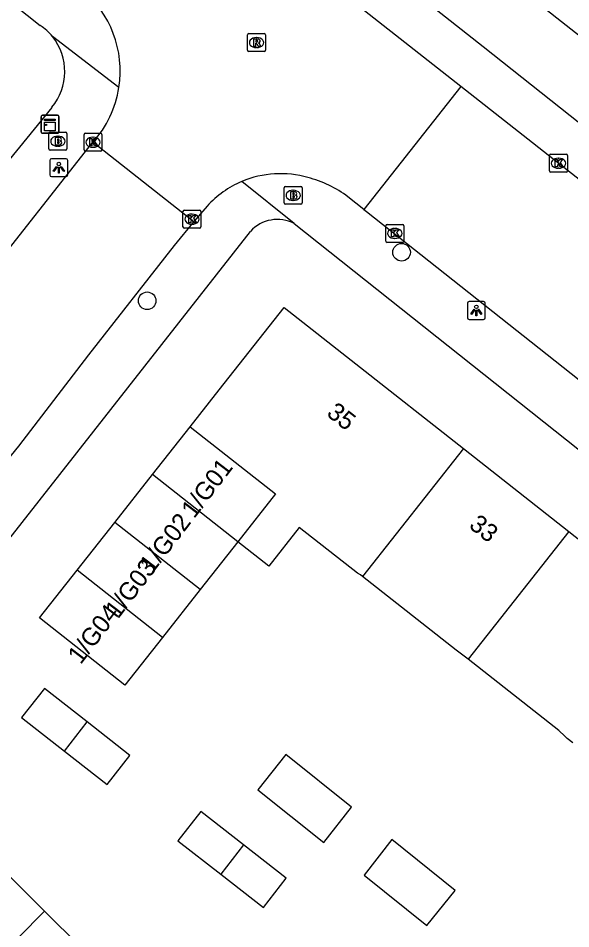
# Model space of a CAD drawing. Extents: x 159222 to 160346, y 381249 to 382166.
# Drawn here: x 160133.8 to 160164.6, y 381881.1 to 381931.9 of the extents above; entities that cross this region are included whole.
import ezdxf

# ---------------------------------------------------------------- set-up
doc = ezdxf.new("R2010")
doc.units = 0
for name, color, linetype in [('IMGEO_Boom', 7, 'Continuous'), ('IMGEO_Brandkraan', 7, 'Continuous'), ('IMGEO_Kast', 7, 'Continuous'), ('IMGEO_Kolk', 7, 'Continuous'), ('IMGEO_Lichtpunt', 7, 'Continuous'), ('IMGEO_Pand', 7, 'Continuous'), ('IMGEO_Pand_nummerreeks', 7, 'Continuous'), ('IMGEO_Rijbaan_lokaal_gesloten', 7, 'Continuous'), ('IMGEO_Rijbaan_lokaal_open', 7, 'Continuous'), ('IMGEO_Rioolput', 7, 'Continuous'), ('IMGEO_Voetpad_open', 7, 'Continuous')]:
    doc.layers.add(name, color=color, linetype=linetype)

msp = doc.modelspace()

# ---------------------------------------------------------------- linework, layer by layer
at = {"layer": 'IMGEO_Boom'}
for centre in [(160155.178, 381918.837), (160140.999, 381916.134)]:
    msp.add_circle(centre, 0.489, dxfattribs=at)
at = {"layer": 'IMGEO_Brandkraan'}
for p, q in [((160135.526, 381924.6), (160135.526, 381925.452)), ((160135.601, 381925.526), (160136.453, 381925.526)), ((160136.014, 381925.306), (160136.039, 381925.306)), ((160136.527, 381925.452), (160136.527, 381924.6)), ((160136.037, 381924.746), (160136.012, 381924.746)), ((160136.453, 381924.526), (160135.601, 381924.526)), ((160148.638, 381921.583), (160148.638, 381922.435)), ((160148.713, 381922.509), (160149.565, 381922.509)), ((160149.126, 381922.289), (160149.151, 381922.289)), ((160149.639, 381922.435), (160149.639, 381921.583)), ((160149.149, 381921.729), (160149.124, 381921.729)), ((160149.565, 381921.509), (160148.713, 381921.509))]:
    msp.add_line(p, q, dxfattribs=at)
for points in [[(160135.526, 381924.6), (160135.526, 381925.452)], [(160135.601, 381925.526), (160136.453, 381925.526)], [(160135.874, 381925.226), (160135.874, 381924.826), (160136.087, 381924.826)], [(160136.105, 381925.226), (160135.874, 381925.226)], [(160136.527, 381925.452), (160136.527, 381924.6)], [(160136.053, 381925.145), (160135.999, 381925.145), (160135.999, 381925.069)], [(160135.999, 381925.069), (160136.052, 381925.069)], [(160136.061, 381924.993), (160135.999, 381924.993), (160135.999, 381924.912)], [(160135.999, 381924.912), (160136.061, 381924.912)], [(160136.453, 381924.526), (160135.601, 381924.526)], [(160148.638, 381921.583), (160148.638, 381922.435)], [(160148.713, 381922.509), (160149.565, 381922.509)], [(160148.986, 381922.209), (160148.986, 381921.809), (160149.199, 381921.809)], [(160149.217, 381922.209), (160148.986, 381922.209)], [(160149.639, 381922.435), (160149.639, 381921.583)], [(160149.165, 381922.128), (160149.111, 381922.128), (160149.111, 381922.052)], [(160149.111, 381922.052), (160149.164, 381922.052)], [(160149.173, 381921.976), (160149.111, 381921.976), (160149.111, 381921.895)], [(160149.111, 381921.895), (160149.173, 381921.895)], [(160149.565, 381921.509), (160148.713, 381921.509)]]:
    msp.add_lwpolyline(points, dxfattribs=at)
for centre, radius, start, end in [((160135.603, 381925.45), 0.0765, 91.552, 178.448), ((160135.603, 381925.45), 0.0765, 91.552, 178.448), ((160136.109, 381925.081), 0.145, 59.4692, 91.5367), ((160136.134, 381925.128), 0.0922, 285.5137, 58.1501), ((160136.451, 381925.45), 0.0765, 1.552, 88.448), ((160136.451, 381925.45), 0.0765, 1.552, 88.448), ((160136.054, 381925.107), 0.0379, 267.8285, 90.9355), ((160136.062, 381924.952), 0.0404, 269.8759, 90.5077), ((160136.093, 381925.077), 0.251, 268.6676, 293.5347), ((160136.139, 381924.936), 0.105, 301.3115, 78.989), ((160135.603, 381924.602), 0.0765, 181.552, 268.448), ((160135.603, 381924.602), 0.0765, 181.552, 268.448), ((160136.451, 381924.602), 0.0765, 271.552, 358.448), ((160136.451, 381924.602), 0.0765, 271.552, 358.448), ((160148.715, 381922.433), 0.0765, 91.552, 178.448), ((160148.715, 381922.433), 0.0765, 91.552, 178.448), ((160149.221, 381922.064), 0.145, 59.4692, 91.5367), ((160149.246, 381922.111), 0.0922, 285.5137, 58.1501), ((160149.563, 381922.433), 0.0765, 1.552, 88.448), ((160149.563, 381922.433), 0.0765, 1.552, 88.448), ((160149.166, 381922.09), 0.0379, 267.8285, 90.9355), ((160149.174, 381921.935), 0.0404, 269.8759, 90.5077), ((160149.205, 381922.06), 0.251, 268.6676, 293.5347), ((160149.251, 381921.919), 0.105, 301.3115, 78.989), ((160148.715, 381921.585), 0.0765, 181.552, 268.448), ((160148.715, 381921.585), 0.0765, 181.552, 268.448), ((160149.563, 381921.585), 0.0765, 271.552, 358.448), ((160149.563, 381921.585), 0.0765, 271.552, 358.448)]:
    msp.add_arc(centre, radius, start, end, dxfattribs=at)
for centre, major_axis, ratio, start_param, end_param in [((160136.013, 381925.026), (-0.387, 0.002), 0.722429, 4.712389, 7.853982), ((160136.038, 381925.026), (-0.39, 0.002), 0.717154, 1.570796, 4.712389), ((160149.125, 381922.009), (-0.387, 0.002), 0.722429, 4.712389, 7.853982), ((160149.15, 381922.009), (-0.39, 0.002), 0.717154, 1.570796, 4.712389)]:
    msp.add_ellipse(centre, major_axis=major_axis, ratio=ratio, start_param=start_param, end_param=end_param, dxfattribs=at)
at = {"layer": 'IMGEO_Kast'}
for p, q in [((160135.086, 381925.546), (160135.086, 381926.387)), ((160135.086, 381926.387), (160135.086, 381925.546)), ((160135.161, 381926.471), (160136.002, 381926.471)), ((160136.002, 381926.471), (160135.161, 381926.471)), ((160136.086, 381926.396), (160136.086, 381925.555)), ((160136.086, 381925.555), (160136.086, 381926.396)), ((160136.011, 381925.471), (160135.17, 381925.471)), ((160135.17, 381925.471), (160136.011, 381925.471))]:
    msp.add_line(p, q, dxfattribs=at)
for points in [[(160135.281, 381926.261), (160135.881, 381926.261), (160135.881, 381926.176), (160135.281, 381926.176), (160135.281, 381926.261)], [(160135.281, 381926.086), (160135.881, 381926.086), (160135.881, 381925.597), (160135.281, 381925.597), (160135.281, 381926.086)]]:
    msp.add_lwpolyline(points, dxfattribs=at)
msp.add_circle((160135.365, 381925.935), 0.0377, dxfattribs=at)
for centre, start, end in [((160135.164, 381926.393), 92.4484, 184.2845), ((160135.164, 381926.393), 92.4484, 184.2845), ((160136.008, 381926.393), 2.4484, 94.2845), ((160136.008, 381926.393), 2.4484, 94.2845), ((160135.164, 381925.549), 182.4484, 274.2845), ((160135.164, 381925.549), 182.4484, 274.2845), ((160136.008, 381925.549), 272.4484, 4.2845), ((160136.008, 381925.549), 272.4484, 4.2845)]:
    msp.add_arc(centre, 0.0779, start, end, dxfattribs=at)
at = {"layer": 'IMGEO_Kolk'}
for p, q in [((160137.482, 381924.544), (160137.482, 381925.396)), ((160137.557, 381925.47), (160138.409, 381925.47)), ((160137.97, 381925.25), (160137.995, 381925.25)), ((160138.483, 381925.396), (160138.483, 381924.544)), ((160137.993, 381924.69), (160137.968, 381924.69)), ((160138.409, 381924.47), (160137.557, 381924.47)), ((160163.423, 381923.372), (160163.423, 381924.224)), ((160163.498, 381924.298), (160164.35, 381924.298)), ((160164.424, 381924.224), (160164.424, 381923.372)), ((160163.911, 381924.078), (160163.936, 381924.078)), ((160164.35, 381923.298), (160163.498, 381923.298)), ((160163.934, 381923.518), (160163.909, 381923.518)), ((160143.072, 381921.181), (160143.924, 381921.181)), ((160142.997, 381920.255), (160142.997, 381921.107)), ((160143.485, 381920.961), (160143.51, 381920.961)), ((160143.998, 381921.107), (160143.998, 381920.255)), ((160143.924, 381920.181), (160143.072, 381920.181)), ((160143.508, 381920.401), (160143.483, 381920.401)), ((160154.3, 381919.463), (160154.3, 381920.315)), ((160154.375, 381920.389), (160155.227, 381920.389)), ((160154.788, 381920.169), (160154.813, 381920.169)), ((160155.301, 381920.315), (160155.301, 381919.463)), ((160154.811, 381919.609), (160154.786, 381919.609)), ((160155.227, 381919.389), (160154.375, 381919.389))]:
    msp.add_line(p, q, dxfattribs=at)
for points in [[(160137.482, 381924.544), (160137.482, 381925.396)], [(160137.557, 381925.47), (160138.409, 381925.47)], [(160138.483, 381925.396), (160138.483, 381924.544)], [(160137.803, 381925.17), (160137.926, 381925.17), (160137.926, 381925.019), (160138.056, 381925.17), (160138.22, 381925.17), (160138.074, 381925.019), (160138.227, 381924.77), (160138.075, 381924.77), (160137.99, 381924.934), (160137.926, 381924.867), (160137.926, 381924.77), (160137.803, 381924.77), (160137.803, 381925.17)], [(160138.409, 381924.47), (160137.557, 381924.47)], [(160163.423, 381923.372), (160163.423, 381924.224)], [(160163.498, 381924.298), (160164.35, 381924.298)], [(160164.424, 381924.224), (160164.424, 381923.372)], [(160163.744, 381923.998), (160163.867, 381923.998), (160163.867, 381923.847), (160163.997, 381923.998), (160164.161, 381923.998), (160164.015, 381923.847), (160164.168, 381923.598), (160164.016, 381923.598), (160163.931, 381923.762), (160163.867, 381923.695), (160163.867, 381923.598), (160163.744, 381923.598), (160163.744, 381923.998)], [(160164.35, 381923.298), (160163.498, 381923.298)], [(160143.072, 381921.181), (160143.924, 381921.181)], [(160142.997, 381920.255), (160142.997, 381921.107)], [(160143.318, 381920.881), (160143.441, 381920.881), (160143.441, 381920.73), (160143.571, 381920.881), (160143.735, 381920.881), (160143.589, 381920.73), (160143.742, 381920.481), (160143.59, 381920.481), (160143.505, 381920.645), (160143.441, 381920.578), (160143.441, 381920.481), (160143.318, 381920.481), (160143.318, 381920.881)], [(160143.998, 381921.107), (160143.998, 381920.255)], [(160143.924, 381920.181), (160143.072, 381920.181)], [(160154.3, 381919.463), (160154.3, 381920.315)], [(160154.375, 381920.389), (160155.227, 381920.389)], [(160155.301, 381920.315), (160155.301, 381919.463)], [(160154.621, 381920.089), (160154.744, 381920.089), (160154.744, 381919.938), (160154.874, 381920.089), (160155.038, 381920.089), (160154.892, 381919.938), (160155.045, 381919.689), (160154.893, 381919.689), (160154.808, 381919.853), (160154.744, 381919.786), (160154.744, 381919.689), (160154.621, 381919.689), (160154.621, 381920.089)], [(160155.227, 381919.389), (160154.375, 381919.389)]]:
    msp.add_lwpolyline(points, dxfattribs=at)
for centre, start, end in [((160137.559, 381925.394), 91.552, 178.448), ((160137.559, 381925.394), 91.552, 178.448), ((160138.407, 381925.394), 1.552, 88.448), ((160138.407, 381925.394), 1.552, 88.448), ((160137.559, 381924.546), 181.552, 268.448), ((160137.559, 381924.546), 181.552, 268.448), ((160138.407, 381924.546), 271.552, 358.448), ((160138.407, 381924.546), 271.552, 358.448), ((160163.5, 381924.222), 91.552, 178.448), ((160163.5, 381924.222), 91.552, 178.448), ((160164.348, 381924.222), 1.552, 88.448), ((160164.348, 381924.222), 1.552, 88.448), ((160163.5, 381923.374), 181.552, 268.448), ((160163.5, 381923.374), 181.552, 268.448), ((160164.348, 381923.374), 271.552, 358.448), ((160164.348, 381923.374), 271.552, 358.448), ((160143.074, 381921.105), 91.552, 178.448), ((160143.074, 381921.105), 91.552, 178.448), ((160143.922, 381921.105), 1.552, 88.448), ((160143.922, 381921.105), 1.552, 88.448), ((160143.074, 381920.257), 181.552, 268.448), ((160143.074, 381920.257), 181.552, 268.448), ((160143.922, 381920.257), 271.552, 358.448), ((160143.922, 381920.257), 271.552, 358.448), ((160154.377, 381920.313), 91.552, 178.448), ((160154.377, 381920.313), 91.552, 178.448), ((160155.225, 381920.313), 1.552, 88.448), ((160155.225, 381920.313), 1.552, 88.448), ((160154.377, 381919.465), 181.552, 268.448), ((160154.377, 381919.465), 181.552, 268.448), ((160155.225, 381919.465), 271.552, 358.448), ((160155.225, 381919.465), 271.552, 358.448)]:
    msp.add_arc(centre, 0.0765, start, end, dxfattribs=at)
for centre, major_axis, ratio, start_param, end_param in [((160137.969, 381924.97), (-0.387, 0.002), 0.722429, 4.712389, 7.853982), ((160137.994, 381924.97), (-0.39, 0.002), 0.717154, 1.570796, 4.712389), ((160163.91, 381923.798), (-0.387, 0.002), 0.722429, 4.712389, 7.853982), ((160163.935, 381923.798), (-0.39, 0.002), 0.717154, 1.570796, 4.712389), ((160143.484, 381920.681), (-0.387, 0.002), 0.722429, 4.712389, 7.853982), ((160143.509, 381920.681), (-0.39, 0.002), 0.717154, 1.570796, 4.712389), ((160154.787, 381919.889), (-0.387, 0.002), 0.722429, 4.712389, 7.853982), ((160154.812, 381919.889), (-0.39, 0.002), 0.717154, 1.570796, 4.712389)]:
    msp.add_ellipse(centre, major_axis=major_axis, ratio=ratio, start_param=start_param, end_param=end_param, dxfattribs=at)
at = {"layer": 'IMGEO_Lichtpunt'}
for p, q in [((160135.577, 381923.956), (160135.577, 381923.149)), ((160135.577, 381923.956), (160135.577, 381923.149)), ((160136.479, 381924.051), (160135.671, 381924.051)), ((160136.479, 381924.051), (160135.671, 381924.051)), ((160136.573, 381923.149), (160136.573, 381923.956)), ((160136.573, 381923.149), (160136.573, 381923.956)), ((160135.671, 381923.055), (160136.479, 381923.055)), ((160135.671, 381923.055), (160136.479, 381923.055)), ((160159.75, 381916.09), (160158.942, 381916.09)), ((160159.75, 381916.09), (160158.942, 381916.09)), ((160158.848, 381915.995), (160158.848, 381915.188)), ((160158.848, 381915.995), (160158.848, 381915.188)), ((160159.844, 381915.188), (160159.844, 381915.995)), ((160159.844, 381915.188), (160159.844, 381915.995)), ((160158.942, 381915.094), (160159.75, 381915.094)), ((160158.942, 381915.094), (160159.75, 381915.094))]:
    msp.add_line(p, q, dxfattribs=at)
for points in [[(160135.951, 381923.62), (160135.99, 381923.592), (160135.802, 381923.33), (160135.764, 381923.357), (160135.951, 381923.62)], [(160136.053, 381923.572), (160136.1, 381923.572), (160136.1, 381923.25), (160136.053, 381923.25), (160136.053, 381923.572)], [(160136.163, 381923.592), (160136.201, 381923.619), (160136.388, 381923.357), (160136.349, 381923.329), (160136.163, 381923.592)], [(160159.222, 381915.659), (160159.261, 381915.631), (160159.073, 381915.369), (160159.035, 381915.396), (160159.222, 381915.659)], [(160159.324, 381915.611), (160159.371, 381915.611), (160159.371, 381915.289), (160159.324, 381915.289), (160159.324, 381915.611)], [(160159.434, 381915.631), (160159.472, 381915.658), (160159.659, 381915.396), (160159.62, 381915.368), (160159.434, 381915.631)]]:
    msp.add_lwpolyline(points, dxfattribs=at)
for centre in [(160136.076, 381923.754), (160159.347, 381915.793)]:
    msp.add_circle(centre, 0.0994, dxfattribs=at)
for centre, start, end in [((160135.671, 381923.956), 90, 180), ((160135.671, 381923.956), 90, 180), ((160136.479, 381923.956), 0, 90), ((160136.479, 381923.956), 0, 90), ((160135.671, 381923.149), 180, 270), ((160135.671, 381923.149), 180, 270), ((160136.479, 381923.149), 270, 0), ((160136.479, 381923.149), 270, 360), ((160158.942, 381915.995), 90, 180), ((160158.942, 381915.995), 90, 180), ((160159.75, 381915.995), 0, 90), ((160159.75, 381915.995), 0, 90), ((160158.942, 381915.188), 180, 270), ((160158.942, 381915.188), 180, 270), ((160159.75, 381915.188), 270, 0), ((160159.75, 381915.188), 270, 360)]:
    msp.add_arc(centre, 0.0946, start, end, dxfattribs=at)
at = {"layer": 'IMGEO_Pand'}
for points in [[(160143.392, 381909.116), (160145.008, 381911.169), (160148.627, 381915.766), (160152.634, 381912.611), (160158.621, 381907.897)], [(160141.289, 381906.445), (160143.392, 381909.116)], [(160143.392, 381909.116), (160148.148, 381905.371), (160146.045, 381902.7)], [(160158.621, 381907.897), (160153.004, 381900.763)], [(160158.621, 381907.897), (160164.49, 381903.277)], [(160139.192, 381903.781), (160141.289, 381906.445)], [(160146.045, 381902.7), (160141.289, 381906.445)], [(160137.094, 381901.117), (160139.192, 381903.781)], [(160143.948, 381900.036), (160139.192, 381903.781)], [(160153.004, 381900.763), (160152.89, 381900.853), (160152.718, 381900.955), (160149.48, 381903.504), (160147.774, 381901.338), (160146.045, 381902.7)], [(160164.49, 381903.277), (160158.887, 381896.159)], [(160164.49, 381903.277), (160170.358, 381898.657)], [(160146.045, 381902.7), (160143.948, 381900.036)], [(160141.851, 381897.372), (160139.754, 381894.708), (160134.997, 381898.453), (160137.094, 381901.117)], [(160141.851, 381897.372), (160137.094, 381901.117)], [(160158.887, 381896.159), (160158.737, 381896.277), (160158.215, 381896.661), (160153.004, 381900.763)], [(160143.948, 381900.036), (160141.851, 381897.372)], [(160164.724, 381891.501), (160164.412, 381891.746), (160164.282, 381891.866), (160163.933, 381892.186), (160158.887, 381896.159)], [(160137.66, 381892.663), (160135.279, 381894.529), (160134.007, 381892.906), (160136.388, 381891.04)], [(160136.388, 381891.04), (160137.66, 381892.663)], [(160136.388, 381891.04), (160138.769, 381889.174), (160140.041, 381890.798), (160137.66, 381892.663)], [(160148.734, 381890.844), (160147.16, 381888.884), (160150.837, 381885.932), (160152.391, 381887.907), (160148.734, 381890.844)], [(160146.368, 381885.806), (160143.985, 381887.665), (160142.715, 381886.038), (160145.099, 381884.178)], [(160135.289, 381882.107), (160131.293, 381886.07)], [(160146.368, 381885.806), (160145.099, 381884.178)], [(160145.099, 381884.178), (160147.483, 381882.319), (160148.752, 381883.946), (160146.368, 381885.806)], [(160154.64, 381886.101), (160153.086, 381884.126), (160156.593, 381881.309), (160158.167, 381883.269), (160154.64, 381886.101)], [(160135.289, 381882.107), (160126.548, 381873.292)], [(160139.285, 381878.145), (160135.289, 381882.107)]]:
    msp.add_lwpolyline(points, dxfattribs=at)
at = {"layer": 'IMGEO_Rijbaan_lokaal_gesloten'}
for points in [[(160158.477, 381928.078), (160142.8, 381940.403)], [(160158.477, 381928.078), (160153.073, 381921.227)], [(160209.912, 381887.8), (160209.032, 381888.323), (160158.477, 381928.078)], [(160137.985, 381924.969), (160143.594, 381920.544)], [(160153.073, 381921.227), (160152.192, 381921.924)], [(160144.344, 381921.409), (160143.594, 381920.544)], [(160153.073, 381921.227), (160153.218, 381921.112), (160181.742, 381898.529), (160186.323, 381894.939), (160188.766, 381893.025), (160205.633, 381879.806)]]:
    msp.add_lwpolyline(points, dxfattribs=at)
for centre, radius, start, end in [((160133.551, 381928.932), 5.948, 351.1983, 50.2182), ((160133.545, 381928.937), 5.954, 318.2121, 351.1617), ((160148.427, 381917.72), 5.496, 73.8236, 112.9915), ((160148.415, 381917.712), 5.499, 112.8487, 137.7605), ((160148.461, 381917.029), 6.155, 52.6839, 75.9224)]:
    msp.add_arc(centre, radius, start, end, dxfattribs=at)
at = {"layer": 'IMGEO_Rijbaan_lokaal_open'}
for points in [[(160002.99, 381786.2), (160012.11, 381795.292), (160116.933, 381899.648), (160120.802, 381903.57), (160121.409, 381904.226), (160123.621, 381906.761), (160125.502, 381909.146), (160137.982, 381924.966), (160137.985, 381924.969)], [(160143.594, 381920.544), (160142.505, 381919.215), (160137.727, 381913.117), (160133.839, 381908.037), (160129.443, 381902.654), (160124.504, 381897.226), (160124.44, 381897.155), (160120.742, 381893.578), (160116.227, 381888.855), (160106.101, 381878.782)]]:
    msp.add_lwpolyline(points, dxfattribs=at)
at = {"layer": 'IMGEO_Rioolput'}
for p, q in [((160146.597, 381930.095), (160146.597, 381930.947)), ((160146.672, 381931.021), (160147.524, 381931.021)), ((160147.085, 381930.801), (160147.11, 381930.801)), ((160147.598, 381930.947), (160147.598, 381930.095)), ((160147.524, 381930.021), (160146.672, 381930.021)), ((160147.108, 381930.241), (160147.083, 381930.241))]:
    msp.add_line(p, q, dxfattribs=at)
for points in [[(160146.597, 381930.095), (160146.597, 381930.947)], [(160146.672, 381931.021), (160147.524, 381931.021)], [(160147.598, 381930.947), (160147.598, 381930.095)], [(160147.186, 381930.719), (160146.934, 381930.721), (160146.934, 381930.321)], [(160146.934, 381930.321), (160147.058, 381930.321), (160147.058, 381930.483), (160147.069, 381930.483)], [(160147.112, 381930.64), (160147.058, 381930.64), (160147.058, 381930.559)], [(160147.058, 381930.559), (160147.11, 381930.559)], [(160147.116, 381930.454), (160147.187, 381930.321), (160147.327, 381930.321), (160147.262, 381930.447)], [(160147.524, 381930.021), (160146.672, 381930.021)]]:
    msp.add_lwpolyline(points, dxfattribs=at)
for centre, radius, start, end in [((160146.674, 381930.945), 0.0765, 91.552, 178.448), ((160146.674, 381930.945), 0.0765, 91.552, 178.448), ((160147.522, 381930.945), 0.0765, 1.552, 88.448), ((160147.522, 381930.945), 0.0765, 1.552, 88.448), ((160147.068, 381930.43), 0.0533, 26.0293, 88.6989), ((160147.094, 381930.748), 0.19, 274.7715, 282.9687), ((160147.118, 381930.544), 0.0964, 77.0061, 93.1865), ((160147.132, 381930.601), 0.0378, 276.6634, 79.6772), ((160147.185, 381930.609), 0.109, 350.3612, 89.416), ((160147.183, 381930.609), 0.112, 277.5842, 350.9817), ((160147.167, 381930.394), 0.108, 29.5134, 73.7905), ((160146.674, 381930.097), 0.0765, 181.552, 268.448), ((160146.674, 381930.097), 0.0765, 181.552, 268.448), ((160147.522, 381930.097), 0.0765, 271.552, 358.448), ((160147.522, 381930.097), 0.0765, 271.552, 358.448)]:
    msp.add_arc(centre, radius, start, end, dxfattribs=at)
for centre, major_axis, ratio, start_param, end_param in [((160147.084, 381930.521), (-0.387, 0.002), 0.722429, 4.712389, 7.853982), ((160147.109, 381930.521), (-0.39, 0.002), 0.717154, 1.570796, 4.712389)]:
    msp.add_ellipse(centre, major_axis=major_axis, ratio=ratio, start_param=start_param, end_param=end_param, dxfattribs=at)
at = {"layer": 'IMGEO_Voetpad_open'}
for points in [[(160120.164, 381966.268), (160212.178, 381893.858), (160212.838, 381893.504)], [(160091.985, 381965.697), (160135.047, 381931.474)], [(160116.887, 381964.196), (160123.544, 381958.928), (160141.712, 381944.521), (160159.725, 381930.297), (160168.874, 381923.038), (160176.929, 381916.708), (160193.834, 381903.352), (160207.982, 381892.133)], [(160139.429, 381928.022), (160135.72, 381930.859)], [(160135.68, 381926.914), (160133.311, 381923.988)], [(160149.197, 381920.443), (160146.28, 381922.78)], [(160149.197, 381920.443), (160193.459, 381885.263), (160212.631, 381870.524)], [(160113.448, 381881.888), (160125.439, 381893.854), (160128.859, 381897.542), (160132.127, 381901.365), (160146.756, 381920.002)]]:
    msp.add_lwpolyline(points, dxfattribs=at)
for centre, radius, start, end in [((160133.334, 381928.923), 3.073, 39.0464, 56.1103), ((160133.325, 381928.911), 3.087, 319.7087, 39.1295), ((160148.267, 381918.614), 2.052, 63.0564, 137.4252)]:
    msp.add_arc(centre, radius, start, end, dxfattribs=at)

# ---------------------------------------------------------------- texts
at = {"layer": 'IMGEO_Pand_nummerreeks'}
for s, rotation, p in [('35', 321.7837, (160150.945, 381909.766)), ('1/G01', 52.6571, (160143.616, 381903.953)), ('1/G02', 52.6571, (160141.288, 381900.901)), ('33', 321.7837, (160158.877, 381903.521)), ('1/G03', 52.6571, (160139.376, 381898.361)), ('1/G04', 52.6571, (160137.293, 381895.82))]:
    msp.add_text(s, height=1, rotation=rotation, dxfattribs=at).set_placement(p)

doc.saveas('drawing.dxf')
